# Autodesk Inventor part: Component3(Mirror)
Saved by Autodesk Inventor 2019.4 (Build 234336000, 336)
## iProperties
Created: 2020-06
Part Number: Component3(Mirror)
Material: Generic
Document SubType Name: Modeling
Designer: Administrator
Density: 1 g/cm^3
Appearance: Default
Title: Component3(Mirror)
Author: Administrator
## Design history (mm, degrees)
